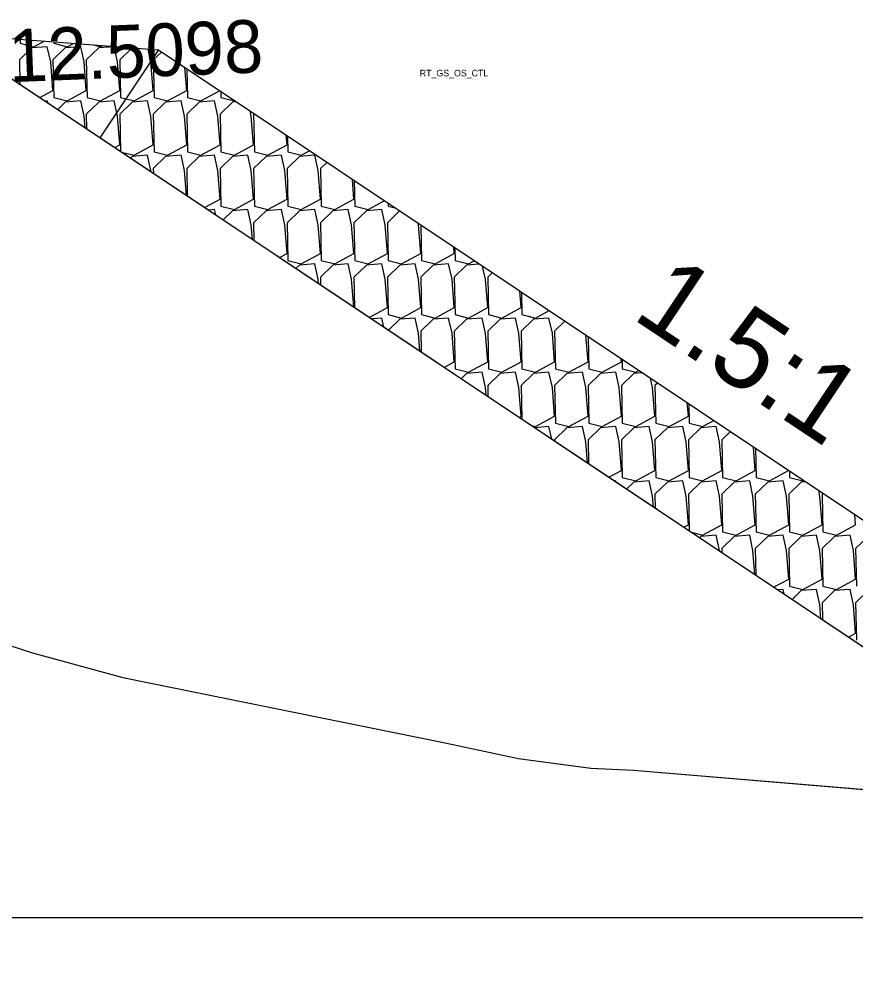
# Model space of a CAD drawing. Extents: x -26 to 2903, y -10 to 63.
# Drawn here: x 2766.86 to 2782.74, y -1.17 to 17.04 of the extents above; entities that cross this region are included whole.
import ezdxf

# ---------------------------------------------------------------- set-up
doc = ezdxf.new("R2010")
doc.units = 0
for name, color, linetype in [('Default', 7, 'Continuous'), ('Exist Cross Section Cell', 7, 'Continuous'), ('Exist XS Ground Line', 7, 'Continuous'), ('Prop CMT Slope Grass', 7, 'Continuous'), ('Prop XS Earthwork Shape', 7, 'Continuous'), ('Prop XS SE Text', 7, 'Continuous'), ('Prop XS Side Slope Text', 7, 'Continuous'), ('Scratch_Level_0', 7, 'Continuous'), ('Scratch_Level_3', 7, 'Continuous')]:
    doc.layers.add(name, color=color, linetype=linetype)

msp = doc.modelspace()

# ---------------------------------------------------------------- linework, layer by layer
at = {"layer": 'Default'}
msp.add_line((2765.416, 16.775), (2792.325, -1.165), dxfattribs=at)
at = {"layer": 'Exist Cross Section Cell'}
msp.add_line((2750, 0), (2900, 0), dxfattribs=at)
at = {"layer": 'Exist XS Ground Line'}
for p, q in [((2765.97, 5.384), (2767.109, 5.022)), ((2767.109, 5.022), (2768.829, 4.549)), ((2768.829, 4.549), (2774.913, 3.32)), ((2774.913, 3.32), (2776.338, 3.016)), ((2776.338, 3.016), (2777.711, 2.83)), ((2777.711, 2.83), (2778.518, 2.792)), ((2778.518, 2.792), (2784.103, 2.328))]:
    msp.add_line(p, q, dxfattribs=at)
at = {"layer": 'Prop CMT Slope Grass'}
msp.add_line((2765.414, 16.776), (2787.227, 2.233), dxfattribs=at)
at = {"layer": 'Prop XS Earthwork Shape'}
msp.add_lwpolyline([(2765.97, 5.384), (2767.109, 5.022), (2768.829, 4.549), (2774.913, 3.32), (2776.338, 3.016), (2777.711, 2.83), (2778.518, 2.792), (2784.103, 2.328), (2785.984, 2.207), (2787.227, 2.233), (2766.568, 16.006)], dxfattribs=at)
at = {"layer": 'Prop XS SE Text'}
for p, q in [((2765.414, 16.776), (2769.5, 16.457)), ((2766.877, 16.661), (2766.879, 16.583)), ((2766.879, 16.583), (2767.134, 16.518)), ((2767.134, 16.518), (2767.332, 16.626)), ((2767.513, 16.612), (2767.514, 16.583)), ((2767.514, 16.583), (2767.769, 16.518)), ((2767.769, 16.518), (2767.887, 16.582)), ((2767.099, 16.495), (2766.863, 16.267)), ((2767.392, 16.518), (2767.099, 16.495)), ((2767.456, 16.229), (2767.392, 16.518)), ((2767.734, 16.495), (2767.498, 16.267)), ((2768.027, 16.518), (2767.734, 16.495)), ((2768.091, 16.229), (2768.027, 16.518)), ((2768.369, 16.495), (2768.133, 16.267)), ((2768.269, 16.553), (2768.404, 16.518)), ((2768.662, 16.518), (2768.369, 16.495)), ((2768.404, 16.518), (2768.442, 16.539)), ((2768.725, 16.229), (2768.662, 16.518)), ((2769.004, 16.495), (2768.768, 16.267)), ((2769.36, 16.229), (2769.307, 16.472)), ((2769.558, 16.417), (2769.403, 16.267)), ((2769.5, 16.457), (2793.435, 0.5)), ((2766.863, 16.267), (2766.873, 15.804)), ((2767.498, 15.687), (2767.456, 16.229)), ((2767.498, 16.267), (2767.514, 15.553)), ((2768.133, 15.687), (2768.091, 16.229)), ((2768.133, 16.267), (2768.149, 15.553)), ((2768.768, 15.687), (2768.725, 16.229)), ((2768.768, 16.267), (2768.783, 15.553)), ((2769.403, 15.687), (2769.36, 16.229)), ((2769.403, 16.267), (2769.418, 15.553)), ((2770.038, 15.687), (2770.004, 16.12)), ((2770.042, 16.095), (2770.053, 15.553)), ((2767.251, 15.552), (2767.498, 15.687)), ((2767.769, 15.489), (2768.133, 15.687)), ((2768.404, 15.489), (2768.768, 15.687)), ((2769.039, 15.489), (2769.403, 15.687)), ((2769.674, 15.489), (2770.038, 15.687)), ((2770.309, 15.489), (2770.663, 15.681)), ((2770.686, 15.666), (2770.688, 15.553)), ((2767.392, 15.489), (2767.351, 15.486)), ((2767.4, 15.453), (2767.392, 15.489)), ((2767.514, 15.553), (2767.769, 15.489)), ((2768.027, 15.489), (2767.734, 15.466)), ((2768.091, 15.199), (2768.027, 15.489)), ((2768.149, 15.553), (2768.404, 15.489)), ((2768.662, 15.489), (2768.369, 15.466)), ((2768.725, 15.199), (2768.662, 15.489)), ((2768.783, 15.553), (2769.039, 15.489)), ((2769.297, 15.489), (2769.004, 15.466)), ((2769.36, 15.199), (2769.297, 15.489)), ((2769.418, 15.553), (2769.674, 15.489)), ((2769.932, 15.489), (2769.639, 15.466)), ((2769.995, 15.199), (2769.932, 15.489)), ((2770.053, 15.553), (2770.309, 15.489)), ((2770.567, 15.489), (2770.274, 15.466)), ((2770.63, 15.199), (2770.567, 15.489)), ((2770.688, 15.553), (2770.944, 15.489)), ((2770.944, 15.489), (2770.948, 15.491)), ((2767.734, 15.466), (2767.59, 15.326)), ((2768.369, 15.466), (2768.133, 15.237)), ((2769.004, 15.466), (2768.768, 15.237)), ((2769.639, 15.466), (2769.403, 15.237)), ((2770.274, 15.466), (2770.038, 15.237)), ((2770.909, 15.466), (2770.673, 15.237)), ((2770.978, 15.471), (2770.909, 15.466)), ((2771.265, 15.199), (2771.245, 15.293)), ((2768.108, 14.981), (2768.091, 15.199)), ((2768.133, 15.237), (2768.139, 14.96)), ((2768.768, 14.657), (2768.725, 15.199)), ((2768.768, 15.237), (2768.783, 14.53)), ((2769.403, 14.657), (2769.36, 15.199)), ((2769.403, 15.237), (2769.418, 14.524)), ((2770.038, 14.657), (2769.995, 15.199)), ((2770.038, 15.237), (2770.053, 14.524)), ((2770.673, 14.657), (2770.63, 15.199)), ((2770.673, 15.237), (2770.688, 14.524)), ((2771.308, 14.657), (2771.265, 15.199)), ((2771.316, 15.245), (2771.308, 15.237)), ((2771.308, 15.237), (2771.323, 14.524)), ((2771.943, 14.657), (2771.929, 14.837)), ((2771.952, 14.822), (2771.958, 14.524)), ((2768.672, 14.605), (2768.768, 14.657)), ((2769.039, 14.459), (2769.403, 14.657)), ((2769.674, 14.459), (2770.038, 14.657)), ((2770.309, 14.459), (2770.673, 14.657)), ((2770.944, 14.459), (2771.308, 14.657)), ((2771.579, 14.459), (2771.943, 14.657)), ((2768.799, 14.52), (2769.039, 14.459)), ((2769.004, 14.436), (2768.972, 14.405)), ((2769.297, 14.459), (2769.004, 14.436)), ((2769.36, 14.17), (2769.297, 14.459)), ((2769.639, 14.436), (2769.403, 14.208)), ((2769.418, 14.524), (2769.674, 14.459)), ((2769.932, 14.459), (2769.639, 14.436)), ((2769.995, 14.17), (2769.932, 14.459)), ((2770.274, 14.436), (2770.038, 14.208)), ((2770.053, 14.524), (2770.309, 14.459)), ((2770.567, 14.459), (2770.274, 14.436)), ((2770.63, 14.17), (2770.567, 14.459)), ((2770.909, 14.436), (2770.673, 14.208)), ((2770.688, 14.524), (2770.944, 14.459)), ((2771.202, 14.459), (2770.909, 14.436)), ((2771.265, 14.17), (2771.202, 14.459)), ((2771.544, 14.436), (2771.308, 14.208)), ((2771.323, 14.524), (2771.579, 14.459)), ((2771.837, 14.459), (2771.544, 14.436)), ((2771.9, 14.17), (2771.837, 14.459)), ((2772.179, 14.436), (2771.943, 14.208)), ((2771.958, 14.524), (2772.214, 14.459)), ((2772.472, 14.459), (2772.179, 14.436)), ((2772.214, 14.459), (2772.369, 14.544)), ((2772.535, 14.17), (2772.472, 14.459)), ((2769.403, 14.208), (2769.405, 14.116)), ((2770.038, 14.208), (2770.049, 13.686)), ((2770.673, 14.208), (2770.688, 13.494)), ((2771.308, 14.208), (2771.323, 13.494)), ((2771.943, 14.208), (2771.958, 13.494)), ((2772.698, 14.324), (2772.578, 14.208)), ((2772.578, 14.208), (2772.593, 13.494)), ((2769.362, 14.144), (2769.36, 14.17)), ((2770.032, 13.698), (2769.995, 14.17)), ((2770.673, 13.628), (2770.63, 14.17)), ((2771.308, 13.628), (2771.265, 14.17)), ((2771.943, 13.628), (2771.9, 14.17)), ((2772.578, 13.628), (2772.535, 14.17)), ((2773.213, 13.628), (2773.183, 14.001)), ((2773.218, 13.978), (2773.228, 13.494)), ((2770.378, 13.467), (2770.673, 13.628)), ((2770.688, 13.494), (2770.944, 13.43)), ((2770.944, 13.43), (2771.308, 13.628)), ((2771.323, 13.494), (2771.579, 13.43)), ((2771.579, 13.43), (2771.943, 13.628)), ((2771.958, 13.494), (2772.214, 13.43)), ((2772.214, 13.43), (2772.578, 13.628)), ((2772.593, 13.494), (2772.849, 13.43)), ((2772.849, 13.43), (2773.213, 13.628)), ((2773.228, 13.494), (2773.484, 13.43)), ((2773.484, 13.43), (2773.79, 13.596)), ((2773.862, 13.548), (2773.863, 13.494)), ((2773.863, 13.494), (2773.992, 13.462)), ((2770.567, 13.43), (2770.448, 13.42)), ((2770.589, 13.326), (2770.567, 13.43)), ((2770.909, 13.407), (2770.73, 13.233)), ((2771.202, 13.43), (2770.909, 13.407)), ((2771.265, 13.14), (2771.202, 13.43)), ((2771.544, 13.407), (2771.308, 13.178)), ((2771.837, 13.43), (2771.544, 13.407)), ((2771.9, 13.14), (2771.837, 13.43)), ((2772.179, 13.407), (2771.943, 13.178)), ((2772.472, 13.43), (2772.179, 13.407)), ((2772.535, 13.14), (2772.472, 13.43)), ((2772.814, 13.407), (2772.578, 13.178)), ((2773.106, 13.43), (2772.814, 13.407)), ((2773.17, 13.14), (2773.106, 13.43)), ((2773.449, 13.407), (2773.213, 13.178)), ((2773.741, 13.43), (2773.449, 13.407)), ((2773.805, 13.14), (2773.741, 13.43)), ((2774.08, 13.403), (2773.848, 13.178)), ((2771.287, 12.861), (2771.265, 13.14)), ((2771.308, 13.178), (2771.315, 12.842)), ((2771.943, 12.598), (2771.9, 13.14)), ((2771.943, 13.178), (2771.958, 12.465)), ((2772.578, 12.598), (2772.535, 13.14)), ((2772.578, 13.178), (2772.593, 12.465)), ((2773.213, 12.598), (2773.17, 13.14)), ((2773.213, 13.178), (2773.228, 12.465)), ((2773.848, 12.598), (2773.805, 13.14)), ((2773.848, 13.178), (2773.863, 12.465)), ((2774.44, 13.14), (2774.434, 13.167)), ((2774.483, 12.598), (2774.44, 13.14)), ((2774.483, 13.134), (2774.498, 12.465)), ((2771.799, 12.52), (2771.943, 12.598)), ((2772.214, 12.4), (2772.578, 12.598)), ((2772.849, 12.4), (2773.213, 12.598)), ((2773.484, 12.4), (2773.848, 12.598)), ((2774.119, 12.4), (2774.483, 12.598)), ((2774.754, 12.4), (2775.117, 12.598)), ((2775.117, 12.598), (2775.108, 12.717)), ((2775.128, 12.704), (2775.133, 12.465)), ((2771.958, 12.465), (2772.214, 12.4)), ((2772.472, 12.4), (2772.179, 12.377)), ((2772.535, 12.11), (2772.472, 12.4)), ((2772.593, 12.465), (2772.849, 12.4)), ((2773.106, 12.4), (2772.814, 12.377)), ((2773.17, 12.11), (2773.106, 12.4)), ((2773.228, 12.465), (2773.484, 12.4)), ((2773.741, 12.4), (2773.449, 12.377)), ((2773.805, 12.11), (2773.741, 12.4)), ((2773.863, 12.465), (2774.119, 12.4)), ((2774.376, 12.4), (2774.084, 12.377)), ((2774.44, 12.11), (2774.376, 12.4)), ((2774.498, 12.465), (2774.754, 12.4)), ((2775.011, 12.4), (2774.718, 12.377)), ((2775.075, 12.11), (2775.011, 12.4)), ((2775.133, 12.465), (2775.389, 12.4)), ((2775.591, 12.396), (2775.353, 12.377)), ((2775.389, 12.4), (2775.496, 12.459)), ((2772.179, 12.377), (2772.111, 12.312)), ((2772.814, 12.377), (2772.578, 12.148)), ((2773.449, 12.377), (2773.213, 12.148)), ((2774.084, 12.377), (2773.848, 12.148)), ((2774.718, 12.377), (2774.483, 12.148)), ((2775.353, 12.377), (2775.117, 12.148)), ((2775.71, 12.11), (2775.657, 12.351)), ((2775.838, 12.231), (2775.752, 12.148)), ((2772.542, 12.025), (2772.535, 12.11)), ((2772.578, 12.148), (2772.581, 11.999)), ((2773.212, 11.578), (2773.17, 12.11)), ((2773.213, 12.148), (2773.225, 11.569)), ((2773.848, 11.568), (2773.805, 12.11)), ((2773.848, 12.148), (2773.863, 11.435)), ((2774.483, 11.568), (2774.44, 12.11)), ((2774.483, 12.148), (2774.498, 11.435)), ((2775.117, 11.568), (2775.075, 12.11)), ((2775.117, 12.148), (2775.133, 11.435)), ((2775.752, 11.568), (2775.71, 12.11)), ((2775.752, 12.148), (2775.768, 11.435)), ((2776.387, 11.568), (2776.363, 11.881)), ((2776.394, 11.86), (2776.403, 11.435)), ((2773.505, 11.382), (2773.848, 11.568)), ((2774.119, 11.37), (2774.483, 11.568)), ((2774.754, 11.37), (2775.117, 11.568)), ((2775.389, 11.37), (2775.752, 11.568)), ((2776.024, 11.37), (2776.387, 11.568)), ((2776.659, 11.37), (2776.917, 11.511)), ((2773.741, 11.37), (2773.546, 11.355)), ((2773.779, 11.2), (2773.741, 11.37)), ((2773.863, 11.435), (2774.119, 11.37)), ((2774.084, 11.347), (2773.869, 11.14)), ((2774.376, 11.37), (2774.084, 11.347)), ((2774.44, 11.081), (2774.376, 11.37)), ((2774.718, 11.347), (2774.483, 11.119)), ((2774.498, 11.435), (2774.754, 11.37)), ((2775.011, 11.37), (2774.718, 11.347)), ((2775.075, 11.081), (2775.011, 11.37)), ((2775.353, 11.347), (2775.117, 11.119)), ((2775.133, 11.435), (2775.389, 11.37)), ((2775.646, 11.37), (2775.353, 11.347)), ((2775.71, 11.081), (2775.646, 11.37)), ((2775.988, 11.347), (2775.752, 11.119)), ((2775.768, 11.435), (2776.024, 11.37)), ((2776.281, 11.37), (2775.988, 11.347)), ((2776.345, 11.081), (2776.281, 11.37)), ((2776.623, 11.347), (2776.387, 11.119)), ((2776.403, 11.435), (2776.659, 11.37)), ((2776.916, 11.37), (2776.623, 11.347)), ((2776.98, 11.081), (2776.916, 11.37)), ((2777.219, 11.31), (2777.022, 11.119)), ((2774.483, 11.119), (2774.491, 10.725)), ((2775.117, 11.119), (2775.133, 10.405)), ((2775.752, 11.119), (2775.768, 10.405)), ((2776.387, 11.119), (2776.403, 10.405)), ((2777.022, 11.119), (2777.038, 10.405)), ((2774.467, 10.741), (2774.44, 11.081)), ((2775.117, 10.539), (2775.075, 11.081)), ((2775.752, 10.539), (2775.71, 11.081)), ((2776.387, 10.539), (2776.345, 11.081)), ((2777.022, 10.539), (2776.98, 11.081)), ((2777.657, 10.539), (2777.617, 11.044)), ((2777.659, 11.016), (2777.673, 10.405)), ((2778.292, 10.539), (2778.288, 10.598)), ((2778.304, 10.587), (2778.307, 10.405)), ((2774.926, 10.435), (2775.117, 10.539)), ((2775.133, 10.405), (2775.389, 10.341)), ((2775.389, 10.341), (2775.752, 10.539)), ((2775.768, 10.405), (2776.024, 10.341)), ((2776.024, 10.341), (2776.387, 10.539)), ((2776.403, 10.405), (2776.659, 10.341)), ((2776.659, 10.341), (2777.022, 10.539)), ((2777.038, 10.405), (2777.293, 10.341)), ((2777.293, 10.341), (2777.657, 10.539)), ((2777.673, 10.405), (2777.928, 10.341)), ((2777.928, 10.341), (2778.292, 10.539)), ((2778.307, 10.405), (2778.563, 10.341)), ((2775.353, 10.318), (2775.251, 10.218)), ((2775.646, 10.341), (2775.353, 10.318)), ((2775.71, 10.051), (2775.646, 10.341)), ((2775.988, 10.318), (2775.752, 10.089)), ((2776.281, 10.341), (2775.988, 10.318)), ((2776.345, 10.051), (2776.281, 10.341)), ((2776.623, 10.318), (2776.387, 10.089)), ((2776.916, 10.341), (2776.623, 10.318)), ((2776.98, 10.051), (2776.916, 10.341)), ((2777.258, 10.318), (2777.022, 10.089)), ((2777.551, 10.341), (2777.258, 10.318)), ((2777.615, 10.051), (2777.551, 10.341)), ((2777.893, 10.318), (2777.657, 10.089)), ((2778.186, 10.341), (2777.893, 10.318)), ((2778.25, 10.051), (2778.186, 10.341)), ((2778.528, 10.318), (2778.292, 10.089)), ((2778.688, 10.33), (2778.528, 10.318)), ((2778.563, 10.341), (2778.624, 10.374)), ((2778.884, 10.051), (2778.846, 10.225)), ((2775.721, 9.905), (2775.71, 10.051)), ((2775.752, 10.089), (2775.757, 9.881)), ((2776.387, 9.509), (2776.345, 10.051)), ((2776.387, 10.089), (2776.401, 9.452)), ((2777.022, 9.509), (2776.98, 10.051)), ((2777.022, 10.089), (2777.038, 9.376)), ((2777.657, 9.509), (2777.615, 10.051)), ((2777.657, 10.089), (2777.673, 9.376)), ((2778.292, 9.509), (2778.25, 10.051)), ((2778.292, 10.089), (2778.307, 9.376)), ((2778.927, 9.509), (2778.884, 10.051)), ((2778.977, 10.138), (2778.927, 10.089)), ((2778.927, 10.089), (2778.942, 9.376)), ((2779.562, 9.509), (2779.542, 9.761)), ((2779.569, 9.743), (2779.577, 9.376)), ((2776.347, 9.487), (2776.387, 9.509)), ((2776.659, 9.311), (2777.022, 9.509)), ((2777.293, 9.311), (2777.657, 9.509)), ((2777.928, 9.311), (2778.292, 9.509)), ((2778.563, 9.311), (2778.927, 9.509)), ((2779.198, 9.311), (2779.562, 9.509)), ((2776.583, 9.33), (2776.659, 9.311)), ((2776.916, 9.311), (2776.644, 9.29)), ((2776.968, 9.073), (2776.916, 9.311)), ((2777.258, 9.288), (2777.022, 9.06)), ((2777.038, 9.376), (2777.293, 9.311)), ((2777.551, 9.311), (2777.258, 9.288)), ((2777.615, 9.022), (2777.551, 9.311)), ((2777.893, 9.288), (2777.657, 9.06)), ((2777.673, 9.376), (2777.928, 9.311)), ((2778.186, 9.311), (2777.893, 9.288)), ((2778.25, 9.022), (2778.186, 9.311)), ((2778.528, 9.288), (2778.292, 9.06)), ((2778.307, 9.376), (2778.563, 9.311)), ((2778.821, 9.311), (2778.528, 9.288)), ((2778.884, 9.022), (2778.821, 9.311)), ((2779.163, 9.288), (2778.927, 9.06)), ((2778.942, 9.376), (2779.198, 9.311)), ((2779.456, 9.311), (2779.163, 9.288)), ((2779.519, 9.022), (2779.456, 9.311)), ((2779.798, 9.288), (2779.562, 9.06)), ((2779.577, 9.376), (2779.833, 9.311)), ((2780.091, 9.311), (2779.798, 9.288)), ((2779.833, 9.311), (2780.045, 9.426)), ((2780.154, 9.022), (2780.091, 9.311)), ((2780.359, 9.217), (2780.197, 9.06)), ((2777.022, 9.06), (2777.023, 9.037)), ((2777.646, 8.622), (2777.615, 9.022)), ((2777.657, 9.06), (2777.667, 8.608)), ((2778.292, 8.479), (2778.25, 9.022)), ((2778.292, 9.06), (2778.307, 8.346)), ((2778.927, 8.479), (2778.884, 9.022)), ((2778.927, 9.06), (2778.942, 8.346)), ((2779.562, 8.479), (2779.519, 9.022)), ((2779.562, 9.06), (2779.577, 8.346)), ((2780.197, 8.479), (2780.154, 9.022)), ((2780.197, 9.06), (2780.212, 8.346)), ((2780.832, 8.479), (2780.797, 8.925)), ((2780.835, 8.899), (2780.847, 8.346)), ((2778.054, 8.35), (2778.292, 8.479)), ((2778.563, 8.282), (2778.927, 8.479)), ((2779.198, 8.282), (2779.562, 8.479)), ((2779.833, 8.282), (2780.197, 8.479)), ((2780.468, 8.282), (2780.832, 8.479)), ((2781.103, 8.282), (2781.466, 8.479)), ((2781.48, 8.469), (2781.482, 8.346)), ((2778.186, 8.282), (2778.159, 8.279)), ((2778.191, 8.258), (2778.186, 8.282)), ((2778.307, 8.346), (2778.563, 8.282)), ((2778.528, 8.259), (2778.39, 8.125)), ((2778.821, 8.282), (2778.528, 8.259)), ((2778.884, 7.992), (2778.821, 8.282)), ((2779.163, 8.259), (2778.927, 8.03)), ((2778.942, 8.346), (2779.198, 8.282)), ((2779.456, 8.282), (2779.163, 8.259)), ((2779.519, 7.992), (2779.456, 8.282)), ((2779.798, 8.259), (2779.562, 8.03)), ((2779.577, 8.346), (2779.833, 8.282)), ((2780.091, 8.282), (2779.798, 8.259)), ((2780.154, 7.992), (2780.091, 8.282)), ((2780.433, 8.259), (2780.197, 8.03)), ((2780.212, 8.346), (2780.468, 8.282)), ((2780.726, 8.282), (2780.433, 8.259)), ((2780.789, 7.992), (2780.726, 8.282)), ((2781.068, 8.259), (2780.832, 8.03)), ((2780.847, 8.346), (2781.103, 8.282)), ((2781.361, 8.282), (2781.068, 8.259)), ((2781.424, 7.992), (2781.361, 8.282)), ((2781.703, 8.259), (2781.467, 8.03)), ((2781.482, 8.346), (2781.738, 8.282)), ((2781.786, 8.265), (2781.703, 8.259)), ((2781.738, 8.282), (2781.751, 8.289)), ((2778.927, 8.03), (2778.933, 7.764)), ((2779.562, 8.03), (2779.577, 7.334)), ((2780.197, 8.03), (2780.212, 7.317)), ((2780.832, 8.03), (2780.847, 7.317)), ((2781.467, 8.03), (2781.482, 7.317)), ((2782.059, 7.992), (2782.036, 8.099)), ((2782.117, 8.045), (2782.102, 8.03)), ((2782.102, 8.03), (2782.117, 7.317)), ((2778.901, 7.785), (2778.884, 7.992)), ((2779.562, 7.45), (2779.519, 7.992)), ((2780.197, 7.45), (2780.154, 7.992)), ((2780.832, 7.45), (2780.789, 7.992)), ((2781.467, 7.45), (2781.424, 7.992)), ((2782.102, 7.45), (2782.059, 7.992)), ((2782.737, 7.45), (2782.722, 7.641)), ((2779.475, 7.402), (2779.562, 7.45)), ((2779.619, 7.306), (2779.833, 7.252)), ((2779.833, 7.252), (2780.197, 7.45)), ((2780.212, 7.317), (2780.468, 7.252)), ((2780.468, 7.252), (2780.832, 7.45)), ((2780.847, 7.317), (2781.103, 7.252)), ((2781.103, 7.252), (2781.467, 7.45)), ((2781.482, 7.317), (2781.738, 7.252)), ((2781.738, 7.252), (2782.102, 7.45)), ((2782.117, 7.317), (2782.373, 7.252)), ((2782.373, 7.252), (2782.737, 7.45)), ((2779.798, 7.229), (2779.772, 7.204)), ((2780.091, 7.252), (2779.798, 7.229)), ((2780.154, 6.962), (2780.091, 7.252)), ((2780.433, 7.229), (2780.197, 7)), ((2780.726, 7.252), (2780.433, 7.229)), ((2780.789, 6.962), (2780.726, 7.252)), ((2781.068, 7.229), (2780.832, 7)), ((2781.361, 7.252), (2781.068, 7.229)), ((2781.424, 6.962), (2781.361, 7.252)), ((2781.703, 7.229), (2781.467, 7)), ((2781.996, 7.252), (2781.703, 7.229)), ((2782.059, 6.962), (2781.996, 7.252)), ((2782.338, 7.229), (2782.102, 7)), ((2782.631, 7.252), (2782.338, 7.229)), ((2782.694, 6.962), (2782.631, 7.252)), ((2782.973, 7.229), (2782.737, 7)), ((2780.155, 6.948), (2780.154, 6.962)), ((2780.197, 7), (2780.199, 6.92)), ((2780.825, 6.502), (2780.789, 6.962)), ((2780.832, 7), (2780.843, 6.49)), ((2781.467, 6.42), (2781.424, 6.962)), ((2781.467, 7), (2781.482, 6.287)), ((2782.102, 6.42), (2782.059, 6.962)), ((2782.102, 7), (2782.117, 6.287)), ((2782.737, 6.42), (2782.694, 6.962)), ((2782.737, 7), (2782.752, 6.287)), ((2781.181, 6.265), (2781.467, 6.42)), ((2781.738, 6.222), (2782.102, 6.42)), ((2782.373, 6.222), (2782.737, 6.42)), ((2781.361, 6.222), (2781.257, 6.214)), ((2781.381, 6.132), (2781.361, 6.222)), ((2781.482, 6.287), (2781.738, 6.222)), ((2781.703, 6.199), (2781.53, 6.032)), ((2781.996, 6.222), (2781.703, 6.199)), ((2782.059, 5.933), (2781.996, 6.222)), ((2782.338, 6.199), (2782.102, 5.971)), ((2782.117, 6.287), (2782.373, 6.222)), ((2782.631, 6.222), (2782.338, 6.199)), ((2782.694, 5.933), (2782.631, 6.222)), ((2782.973, 6.199), (2782.737, 5.971)), ((2782.08, 5.665), (2782.059, 5.933)), ((2782.102, 5.971), (2782.109, 5.646)), ((2782.737, 5.391), (2782.694, 5.933)), ((2782.737, 5.971), (2782.752, 5.257)), ((2782.602, 5.317), (2782.737, 5.391))]:
    msp.add_line(p, q, dxfattribs=at)
at = {"layer": 'Scratch_Level_3'}
msp.add_line((2769.5, 16.457), (2768.39, 14.792), dxfattribs=at)

# ---------------------------------------------------------------- texts
at = {"layer": 'Default'}
msp.add_text('12.5098', height=1, rotation=2.279, dxfattribs=at).set_placement((2766.675, 15.844))
at = {"layer": 'Prop XS Side Slope Text'}
msp.add_text('1.5:1', height=1.5, rotation=326.3079, dxfattribs=at).set_placement((2778.466, 11.38))
at = {"layer": 'Scratch_Level_0'}
msp.add_text('RT_GS_OS_CTL', height=0.125, dxfattribs=at).set_placement((2774.463, 15.955))
msp.add_text('RT_GS_OS_CTL', height=0.125, dxfattribs=at).set_placement((2774.463, 15.955))

doc.saveas('drawing.dxf')
